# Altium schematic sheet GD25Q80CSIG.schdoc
size 127 x 101 mm
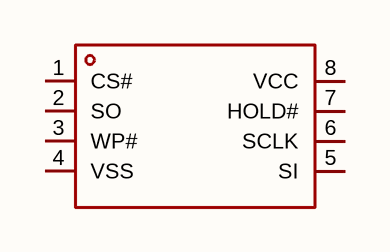
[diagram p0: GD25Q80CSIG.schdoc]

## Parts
U?  gd25q80csig  [SOP-8_L5.3-W5.3-P1.27-LS8.0-BL]  (value not drawn)

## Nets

Not connected (* = marked no-connect by the designer): U? 1(CS#) 2(SO) 3(WP#) 4(VSS) 5(SI) 6(SCLK) 7(HOLD#) 8(VCC)

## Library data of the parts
U? = gd25q80csig: 接口类型:SPI;存储容量:8Mbit;时钟频率(fc):120MHz;; Manufacturer: GigaDevice(兆易创新); AddInBom: yes; ModelId: e456afcfff5840a795bdd4917416584f; ModelName: SOP-8_L5.2-W5.3-H2.1-LS7.9-P1.27; ModelTransform: 311.024,204.724,0,90,0,0,0,0.0005,0; Interface: SPI; Memory Size: 8Mbit; Clock Frequency: 120MHz; Voltage - Supply: 2.7V~3.6V; Standby Supply Current: 1uA; Program / Erase Cycles: 100000次; Page Programming Time (Tpp): 600us; Block Erase Time(tBE): 150ms@(32KB); Data Retention - TDR (Year): 20年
